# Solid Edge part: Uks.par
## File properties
Author: Türk
Template: iso part.par
Last saved by: Türk
Revision: 41
Application: Solid Edge
Accuracy: 0,990
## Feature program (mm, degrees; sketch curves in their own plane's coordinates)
base feature "unnamed BaseFeature 1"
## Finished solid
Body 1: sheet body, 4 faces, 13 edges, 10 vertices.
  Faces by surface: spline 4
  Edges by curve: spline 7, line 5, curve on surface 1
Body 2: sheet body, 2 faces, 7 edges, 6 vertices.
  Faces by surface: spline 2
  Edges by curve: spline 5, intersection 1, line 1
Body 3: sheet body, 4 faces, 13 edges, 10 vertices.
  Faces by surface: offset 3, spline 1
  Edges by curve: curve on surface 13
Body 4: sheet body, 5 faces, 17 edges, 14 vertices.
  Faces by surface: spline 5
  Edges by curve: spline 11, line 3, curve on surface 2, intersection 1
Body 5: sheet body, 1 face, 4 edges, 4 vertices.
  Faces by surface: plane 1
  Edges by curve: line 4
Body 6: solid body, 127 faces, 381 edges, 252 vertices.
  Faces by surface: plane 60, spline 30, swept 14, blend 12, offset 7, cylinder 3, sphere 1
  Edges by curve: intersection 153, line 144, spline 45, curve on surface 29, circle 7, ellipse 3
Bounding box of the edges (mm; curved faces can reach further): 941.034 x 1000.759 x 806.222, from (-1039.9013, 1099.7363, 144.8721) to (-98.8677, 2100.4958, 951.0944).
Cylindrical faces by radius (mm): R746.2548 x1, R1779.5305 x1, R73875.9026 x1
Spherical faces by radius (mm): R5 x1
Planar faces by outward normal: +x 5, +y 9, +z 2, -x 6, -y 6, -z 5, oblique 27
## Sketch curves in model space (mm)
spline (-369.7089, 2055, 867.877) -> (-394.6294, 2055, 865.3378) -> (-418.7085, 2055, 862.1057)
line (-361.3211, 2055, 870.9469) -> (-369.7089, 2055, 867.877)
line (-361.3211, 2055, 870.9469) -> (-418.7085, 2055, 862.1057)
line (-627.936, 2100, 550.3908) -> (-627.936, 2100, 550)
line (-637.936, 2100, 551.622) -> (-637.936, 2100, 550)
line (-632.936, 2100, 550) -> (-632.936, 2100, 551.0089)
line (-100, 1100, 951.0944) -> (-99.6282, 1100, 951.0944)
line (-100, 1676.7991, 916.0316) -> (-100, 1674.9448, 916.0944)
line (-100, 2083.5349, 846.0113) -> (-100, 2076.6639, 849.6743)
line (-376.1025, 1100, 912.3275) -> (-327.1964, 1100, 920.2703)
spline (-754.5468, 1100, 200.7849) -> (-754.5202, 1100, 200.7837) -> (-754.4935, 1100, 200.7827)
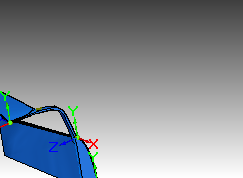
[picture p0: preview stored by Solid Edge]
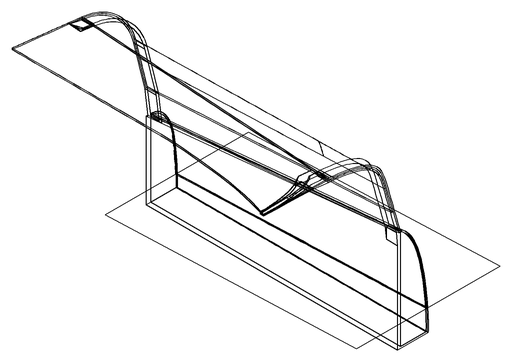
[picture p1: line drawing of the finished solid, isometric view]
